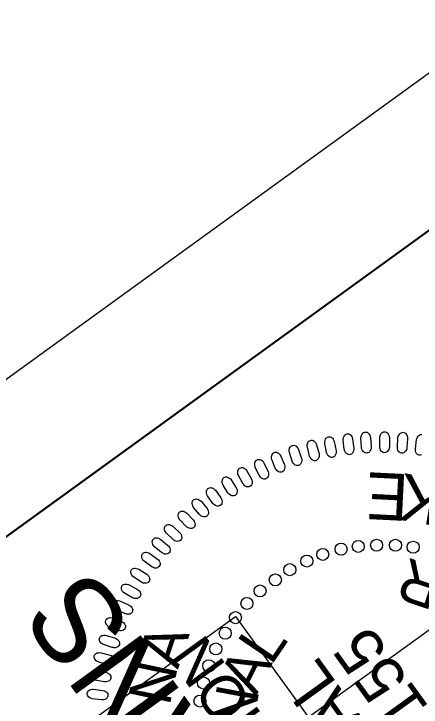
# Model space of a CAD drawing. Extents: x 474925 to 478950, y 494687 to 502905.
# Drawn here: x 475015.1 to 475069.3, y 502284.1 to 502376.4 of the extents above; entities that cross this region are included whole.
import ezdxf

# ---------------------------------------------------------------- set-up
doc = ezdxf.new("R2010")
doc.units = 0
for name, color, linetype in [('Sheet PE Seal Cell', 7, 'Continuous'), ('Sheet Plan CELL', 7, 'Continuous'), ('Sheet Plot Border Inside CELL', 7, 'Continuous'), ('Sheet Plot Border Outside CELL', 7, 'Continuous'), ('Sheet Sticker Incomplete CELL', 7, 'Continuous')]:
    doc.layers.add(name, color=color, linetype=linetype)

msp = doc.modelspace()

# ---------------------------------------------------------------- linework, layer by layer
at = {"layer": 'Sheet PE Seal Cell'}
for points in [[(475061.38, 502318.68), (475061.305, 502319.905), (475061.329, 502320.126), (475061.372, 502320.268), (475061.474, 502320.445), (475061.564, 502320.56), (475061.672, 502320.647), (475061.774, 502320.692), (475061.885, 502320.719), (475061.997, 502320.706), (475062.119, 502320.684), (475062.227, 502320.63), (475062.337, 502320.537), (475062.402, 502320.461), (475062.478, 502320.315), (475062.549, 502320.14), (475062.581, 502319.982), (475062.665, 502318.728), (475062.652, 502318.558), (475062.616, 502318.416), (475062.537, 502318.251), (475062.433, 502318.105), (475062.341, 502318.019), (475062.188, 502317.95), (475062.04, 502317.921), (475061.889, 502317.952), (475061.781, 502317.995), (475061.648, 502318.087), (475061.518, 502318.249), (475061.44, 502318.424), (475061.402, 502318.552)], [(475063.81, 502318.76), (475063.813, 502319.987), (475063.851, 502320.206), (475063.903, 502320.346), (475064.015, 502320.515), (475064.113, 502320.624), (475064.226, 502320.704), (475064.33, 502320.744), (475064.442, 502320.763), (475064.554, 502320.743), (475064.674, 502320.713), (475064.778, 502320.654), (475064.882, 502320.553), (475064.943, 502320.473), (475065.01, 502320.323), (475065.069, 502320.144), (475065.091, 502319.984), (475065.096, 502318.728), (475065.073, 502318.558), (475065.028, 502318.419), (475064.938, 502318.259), (475064.826, 502318.12), (475064.729, 502318.04), (475064.571, 502317.98), (475064.422, 502317.961), (475064.273, 502318.001), (475064.168, 502318.051), (475064.04, 502318.151), (475063.921, 502318.321), (475063.855, 502318.501), (475063.825, 502318.63)], [(475066.158, 502318.725), (475066.237, 502319.949), (475066.288, 502320.165), (475066.349, 502320.302), (475066.472, 502320.464), (475066.576, 502320.567), (475066.694, 502320.639), (475066.8, 502320.672), (475066.914, 502320.684), (475067.024, 502320.657), (475067.142, 502320.62), (475067.242, 502320.554), (475067.34, 502320.447), (475067.395, 502320.363), (475067.452, 502320.21), (475067.5, 502320.027), (475067.512, 502319.866), (475067.439, 502318.612), (475067.405, 502318.444), (475067.351, 502318.308), (475067.252, 502318.155), (475067.131, 502318.022), (475067.028, 502317.949), (475066.868, 502317.899), (475066.717, 502317.89), (475066.571, 502317.939), (475066.47, 502317.995), (475066.349, 502318.103), (475066.241, 502318.28), (475066.185, 502318.463), (475066.164, 502318.595)], [(475056.729, 502318.011), (475056.501, 502319.216), (475056.498, 502319.439), (475056.523, 502319.585), (475056.602, 502319.773), (475056.677, 502319.899), (475056.772, 502319.998), (475056.867, 502320.057), (475056.974, 502320.097), (475057.088, 502320.098), (475057.211, 502320.09), (475057.325, 502320.052), (475057.446, 502319.973), (475057.52, 502319.906), (475057.614, 502319.771), (475057.705, 502319.606), (475057.757, 502319.453), (475057.998, 502318.22), (475058.007, 502318.049), (475057.989, 502317.903), (475057.93, 502317.73), (475057.846, 502317.572), (475057.766, 502317.476), (475057.622, 502317.388), (475057.479, 502317.34), (475057.325, 502317.352), (475057.213, 502317.382), (475057.069, 502317.456), (475056.92, 502317.601), (475056.821, 502317.764), (475056.768, 502317.886)], [(475059.084, 502318.421), (475058.932, 502319.638), (475058.942, 502319.86), (475058.977, 502320.006), (475059.067, 502320.188), (475059.15, 502320.309), (475059.252, 502320.402), (475059.35, 502320.454), (475059.459, 502320.488), (475059.573, 502320.482), (475059.695, 502320.467), (475059.806, 502320.421), (475059.923, 502320.334), (475059.992, 502320.263), (475060.077, 502320.122), (475060.158, 502319.951), (475060.201, 502319.797), (475060.363, 502318.55), (475060.362, 502318.379), (475060.335, 502318.235), (475060.265, 502318.066), (475060.171, 502317.913), (475060.084, 502317.822), (475059.937, 502317.743), (475059.79, 502317.705), (475059.637, 502317.726), (475059.527, 502317.763), (475059.388, 502317.846), (475059.249, 502317.999), (475059.16, 502318.17), (475059.114, 502318.294)], [(475052.158, 502316.828), (475051.781, 502317.996), (475051.749, 502318.217), (475051.756, 502318.366), (475051.811, 502318.561), (475051.869, 502318.695), (475051.952, 502318.806), (475052.039, 502318.876), (475052.139, 502318.929), (475052.252, 502318.945), (475052.376, 502318.953), (475052.493, 502318.929), (475052.624, 502318.865), (475052.705, 502318.808), (475052.815, 502318.686), (475052.927, 502318.534), (475052.998, 502318.389), (475053.39, 502317.195), (475053.421, 502317.027), (475053.421, 502316.88), (475053.385, 502316.701), (475053.321, 502316.534), (475053.254, 502316.428), (475053.122, 502316.323), (475052.985, 502316.258), (475052.832, 502316.25), (475052.717, 502316.265), (475052.565, 502316.321), (475052.399, 502316.446), (475052.28, 502316.596), (475052.212, 502316.71)], [(475054.473, 502317.516), (475054.17, 502318.705), (475054.152, 502318.926), (475054.168, 502319.074), (475054.235, 502319.267), (475054.302, 502319.397), (475054.391, 502319.502), (475054.483, 502319.566), (475054.587, 502319.613), (475054.7, 502319.622), (475054.823, 502319.622), (475054.94, 502319.59), (475055.066, 502319.519), (475055.144, 502319.456), (475055.245, 502319.328), (475055.348, 502319.169), (475055.409, 502319.02), (475055.726, 502317.804), (475055.746, 502317.634), (475055.737, 502317.488), (475055.689, 502317.311), (475055.616, 502317.148), (475055.541, 502317.046), (475055.404, 502316.95), (475055.264, 502316.894), (475055.109, 502316.896), (475054.995, 502316.918), (475054.847, 502316.983), (475054.69, 502317.118), (475054.58, 502317.276), (475054.52, 502317.394)], [(475049.905, 502315.904), (475049.456, 502317.046), (475049.411, 502317.264), (475049.407, 502317.413), (475049.45, 502317.612), (475049.5, 502317.749), (475049.576, 502317.865), (475049.658, 502317.94), (475049.755, 502317.999), (475049.866, 502318.022), (475049.989, 502318.038), (475050.108, 502318.021), (475050.242, 502317.966), (475050.327, 502317.914), (475050.445, 502317.799), (475050.566, 502317.654), (475050.645, 502317.514), (475051.113, 502316.348), (475051.154, 502316.181), (475051.163, 502316.035), (475051.138, 502315.854), (475051.085, 502315.683), (475051.024, 502315.574), (475050.9, 502315.46), (475050.768, 502315.386), (475050.614, 502315.369), (475050.498, 502315.377), (475050.343, 502315.423), (475050.17, 502315.537), (475050.041, 502315.68), (475049.967, 502315.789)], [(475047.761, 502314.946), (475047.241, 502316.057), (475047.182, 502316.271), (475047.169, 502316.419), (475047.199, 502316.621), (475047.241, 502316.762), (475047.308, 502316.881), (475047.386, 502316.962), (475047.48, 502317.028), (475047.589, 502317.057), (475047.71, 502317.08), (475047.831, 502317.071), (475047.968, 502317.024), (475048.056, 502316.978), (475048.18, 502316.871), (475048.31, 502316.734), (475048.398, 502316.599), (475048.938, 502315.464), (475048.989, 502315.301), (475049.008, 502315.155), (475048.994, 502314.973), (475048.952, 502314.799), (475048.898, 502314.685), (475048.781, 502314.565), (475048.654, 502314.483), (475048.502, 502314.456), (475048.386, 502314.457), (475048.229, 502314.493), (475048.049, 502314.596), (475047.911, 502314.73), (475047.83, 502314.835)], [(475045.595, 502313.867), (475045.006, 502314.944), (475044.933, 502315.154), (475044.912, 502315.301), (475044.928, 502315.505), (475044.961, 502315.647), (475045.021, 502315.77), (475045.094, 502315.856), (475045.183, 502315.927), (475045.291, 502315.963), (475045.41, 502315.994), (475045.53, 502315.992), (475045.67, 502315.955), (475045.761, 502315.914), (475045.892, 502315.815), (475046.03, 502315.686), (475046.127, 502315.557), (475046.736, 502314.458), (475046.799, 502314.298), (475046.826, 502314.154), (475046.824, 502313.972), (475046.793, 502313.795), (475046.746, 502313.679), (475046.636, 502313.551), (475046.515, 502313.462), (475046.364, 502313.425), (475046.249, 502313.418), (475046.089, 502313.444), (475045.904, 502313.536), (475045.758, 502313.661), (475045.67, 502313.761)], [(475043.602, 502312.63), (475042.946, 502313.667), (475042.861, 502313.872), (475042.83, 502314.018), (475042.834, 502314.222), (475042.858, 502314.367), (475042.91, 502314.493), (475042.977, 502314.583), (475043.062, 502314.66), (475043.167, 502314.703), (475043.284, 502314.741), (475043.404, 502314.747), (475043.546, 502314.718), (475043.639, 502314.683), (475043.776, 502314.592), (475043.923, 502314.472), (475044.027, 502314.349), (475044.705, 502313.291), (475044.776, 502313.136), (475044.812, 502312.994), (475044.822, 502312.811), (475044.802, 502312.634), (475044.763, 502312.514), (475044.662, 502312.379), (475044.546, 502312.282), (475044.398, 502312.237), (475044.283, 502312.223), (475044.123, 502312.239), (475043.931, 502312.319), (475043.778, 502312.435), (475043.684, 502312.528)], [(475041.605, 502311.225), (475040.886, 502312.219), (475040.788, 502312.419), (475040.748, 502312.563), (475040.74, 502312.766), (475040.754, 502312.912), (475040.799, 502313.042), (475040.86, 502313.135), (475040.939, 502313.217), (475041.042, 502313.267), (475041.156, 502313.313), (475041.276, 502313.326), (475041.419, 502313.306), (475041.514, 502313.277), (475041.657, 502313.195), (475041.81, 502313.085), (475041.922, 502312.969), (475042.665, 502311.955), (475042.746, 502311.805), (475042.791, 502311.664), (475042.812, 502311.483), (475042.803, 502311.304), (475042.771, 502311.182), (475042.679, 502311.042), (475042.57, 502310.938), (475042.425, 502310.883), (475042.311, 502310.862), (475042.15, 502310.868), (475041.954, 502310.936), (475041.794, 502311.042), (475041.693, 502311.129)], [(475039.805, 502309.738), (475039.026, 502310.685), (475038.915, 502310.878), (475038.866, 502311.018), (475038.845, 502311.221), (475038.85, 502311.367), (475038.886, 502311.5), (475038.942, 502311.597), (475039.015, 502311.684), (475039.115, 502311.74), (475039.226, 502311.793), (475039.345, 502311.813), (475039.489, 502311.803), (475039.586, 502311.779), (475039.733, 502311.707), (475039.894, 502311.606), (475040.012, 502311.498), (475040.817, 502310.532), (475040.907, 502310.387), (475040.961, 502310.25), (475040.994, 502310.071), (475040.996, 502309.892), (475040.972, 502309.768), (475040.889, 502309.622), (475040.786, 502309.512), (475040.645, 502309.448), (475040.532, 502309.419), (475040.371, 502309.416), (475040.171, 502309.47), (475040.005, 502309.566), (475039.9, 502309.647)], [(475038.033, 502308.154), (475037.195, 502309.05), (475037.073, 502309.235), (475037.015, 502309.373), (475036.981, 502309.573), (475036.977, 502309.72), (475037.004, 502309.855), (475037.053, 502309.955), (475037.122, 502310.046), (475037.217, 502310.108), (475037.325, 502310.168), (475037.443, 502310.197), (475037.587, 502310.195), (475037.685, 502310.177), (475037.837, 502310.114), (475038.003, 502310.024), (475038.129, 502309.923), (475038.993, 502309.01), (475039.091, 502308.871), (475039.154, 502308.738), (475039.198, 502308.561), (475039.211, 502308.382), (475039.195, 502308.257), (475039.121, 502308.106), (475039.025, 502307.989), (475038.889, 502307.917), (475038.779, 502307.882), (475038.618, 502307.868), (475038.414, 502307.91), (475038.243, 502307.995), (475038.132, 502308.07)], [(475036.291, 502306.401), (475035.398, 502307.242), (475035.264, 502307.42), (475035.198, 502307.553), (475035.152, 502307.752), (475035.139, 502307.897), (475035.157, 502308.034), (475035.2, 502308.137), (475035.263, 502308.233), (475035.354, 502308.3), (475035.459, 502308.367), (475035.573, 502308.402), (475035.717, 502308.41), (475035.817, 502308.399), (475035.972, 502308.345), (475036.144, 502308.265), (475036.275, 502308.172), (475037.195, 502307.315), (475037.302, 502307.183), (475037.373, 502307.055), (475037.427, 502306.88), (475037.452, 502306.703), (475037.444, 502306.577), (475037.38, 502306.421), (475037.291, 502306.299), (475037.16, 502306.218), (475037.052, 502306.176), (475036.892, 502306.152), (475036.687, 502306.181), (475036.509, 502306.255), (475036.395, 502306.323)], [(475034.764, 502304.666), (475033.82, 502305.45), (475033.676, 502305.618), (475033.601, 502305.748), (475033.542, 502305.943), (475033.52, 502306.087), (475033.53, 502306.224), (475033.567, 502306.33), (475033.623, 502306.429), (475033.71, 502306.503), (475033.81, 502306.576), (475033.921, 502306.618), (475034.066, 502306.635), (475034.165, 502306.63), (475034.323, 502306.586), (475034.5, 502306.517), (475034.637, 502306.433), (475035.608, 502305.636), (475035.724, 502305.51), (475035.803, 502305.386), (475035.868, 502305.215), (475035.904, 502305.04), (475035.904, 502304.914), (475035.849, 502304.755), (475035.769, 502304.628), (475035.643, 502304.538), (475035.538, 502304.49), (475035.38, 502304.455), (475035.173, 502304.472), (475034.992, 502304.535), (475034.873, 502304.595)], [(475033.441, 502302.788), (475032.449, 502303.511), (475032.294, 502303.671), (475032.212, 502303.795), (475032.141, 502303.986), (475032.109, 502304.129), (475032.111, 502304.267), (475032.141, 502304.374), (475032.191, 502304.477), (475032.273, 502304.556), (475032.368, 502304.635), (475032.477, 502304.684), (475032.62, 502304.709), (475032.72, 502304.711), (475032.881, 502304.677), (475033.06, 502304.62), (475033.203, 502304.544), (475034.223, 502303.809), (475034.346, 502303.691), (475034.432, 502303.572), (475034.508, 502303.406), (475034.555, 502303.234), (475034.562, 502303.108), (475034.518, 502302.945), (475034.446, 502302.813), (475034.325, 502302.716), (475034.224, 502302.661), (475034.068, 502302.617), (475033.861, 502302.62), (475033.676, 502302.671), (475033.554, 502302.724)], [(475032.079, 502300.723), (475031.044, 502301.382), (475030.88, 502301.532), (475030.789, 502301.65), (475030.707, 502301.836), (475030.667, 502301.977), (475030.66, 502302.115), (475030.682, 502302.224), (475030.726, 502302.33), (475030.803, 502302.413), (475030.893, 502302.498), (475030.999, 502302.554), (475031.14, 502302.589), (475031.239, 502302.597), (475031.401, 502302.573), (475031.585, 502302.527), (475031.731, 502302.46), (475032.795, 502301.791), (475032.926, 502301.681), (475033.02, 502301.568), (475033.106, 502301.407), (475033.163, 502301.237), (475033.179, 502301.112), (475033.144, 502300.947), (475033.081, 502300.811), (475032.967, 502300.706), (475032.868, 502300.645), (475032.716, 502300.591), (475032.509, 502300.582), (475032.321, 502300.621), (475032.196, 502300.666)], [(475030.903, 502298.662), (475029.829, 502299.255), (475029.655, 502299.394), (475029.558, 502299.507), (475029.464, 502299.687), (475029.415, 502299.825), (475029.399, 502299.962), (475029.415, 502300.073), (475029.452, 502300.181), (475029.523, 502300.269), (475029.607, 502300.359), (475029.71, 502300.422), (475029.848, 502300.465), (475029.947, 502300.479), (475030.111, 502300.466), (475030.296, 502300.431), (475030.447, 502300.374), (475031.551, 502299.773), (475031.688, 502299.671), (475031.789, 502299.564), (475031.884, 502299.409), (475031.953, 502299.243), (475031.976, 502299.12), (475031.952, 502298.953), (475031.897, 502298.812), (475031.79, 502298.701), (475031.696, 502298.634), (475031.547, 502298.57), (475031.341, 502298.548), (475031.151, 502298.576), (475031.023, 502298.613)], [(475029.865, 502296.543), (475028.756, 502297.068), (475028.574, 502297.196), (475028.47, 502297.302), (475028.364, 502297.476), (475028.307, 502297.611), (475028.283, 502297.747), (475028.292, 502297.858), (475028.321, 502297.968), (475028.387, 502298.061), (475028.465, 502298.156), (475028.564, 502298.225), (475028.699, 502298.277), (475028.796, 502298.297), (475028.961, 502298.294), (475029.148, 502298.271), (475029.302, 502298.223), (475030.441, 502297.693), (475030.585, 502297.6), (475030.693, 502297.499), (475030.798, 502297.35), (475030.876, 502297.19), (475030.907, 502297.067), (475030.894, 502296.9), (475030.848, 502296.756), (475030.748, 502296.638), (475030.659, 502296.565), (475030.514, 502296.492), (475030.309, 502296.457), (475030.118, 502296.473), (475029.988, 502296.502)], [(475028.944, 502294.32), (475027.805, 502294.773), (475027.614, 502294.89), (475027.504, 502294.99), (475027.388, 502295.156), (475027.322, 502295.288), (475027.289, 502295.421), (475027.291, 502295.533), (475027.314, 502295.645), (475027.374, 502295.741), (475027.446, 502295.842), (475027.54, 502295.916), (475027.672, 502295.977), (475027.768, 502296.003), (475027.932, 502296.01), (475028.121, 502295.999), (475028.277, 502295.961), (475029.447, 502295.504), (475029.596, 502295.42), (475029.709, 502295.326), (475029.825, 502295.184), (475029.913, 502295.028), (475029.951, 502294.908), (475029.949, 502294.74), (475029.912, 502294.594), (475029.82, 502294.47), (475029.735, 502294.391), (475029.595, 502294.31), (475029.393, 502294.261), (475029.201, 502294.266), (475029.07, 502294.286)], [(475028.189, 502292.044), (475027.024, 502292.426), (475026.827, 502292.529), (475026.71, 502292.622), (475026.583, 502292.782), (475026.51, 502292.908), (475026.469, 502293.039), (475026.463, 502293.151), (475026.479, 502293.264), (475026.533, 502293.365), (475026.599, 502293.469), (475026.688, 502293.55), (475026.815, 502293.618), (475026.91, 502293.65), (475027.073, 502293.668), (475027.262, 502293.669), (475027.421, 502293.641), (475028.617, 502293.257), (475028.771, 502293.183), (475028.891, 502293.097), (475029.014, 502292.962), (475029.112, 502292.812), (475029.158, 502292.695), (475029.166, 502292.527), (475029.138, 502292.378), (475029.054, 502292.249), (475028.974, 502292.165), (475028.84, 502292.075), (475028.641, 502292.014), (475028.45, 502292.006), (475028.317, 502292.018)], [(475027.57, 502289.792), (475026.382, 502290.1), (475026.179, 502290.191), (475026.057, 502290.277), (475025.921, 502290.428), (475025.839, 502290.55), (475025.79, 502290.678), (475025.777, 502290.789), (475025.786, 502290.903), (475025.834, 502291.006), (475025.893, 502291.115), (475025.977, 502291.201), (475026.1, 502291.277), (475026.192, 502291.315), (475026.354, 502291.343), (475026.542, 502291.355), (475026.702, 502291.338), (475027.921, 502291.03), (475028.079, 502290.966), (475028.203, 502290.887), (475028.335, 502290.76), (475028.442, 502290.617), (475028.495, 502290.503), (475028.514, 502290.336), (475028.495, 502290.186), (475028.419, 502290.052), (475028.345, 502289.963), (475028.217, 502289.864), (475028.023, 502289.791), (475027.832, 502289.771), (475027.699, 502289.775)], [(475027.1, 502287.463), (475025.896, 502287.695), (475025.688, 502287.773), (475025.56, 502287.851), (475025.415, 502287.993), (475025.326, 502288.109), (475025.269, 502288.234), (475025.249, 502288.345), (475025.251, 502288.459), (475025.292, 502288.565), (475025.344, 502288.677), (475025.422, 502288.768), (475025.54, 502288.852), (475025.63, 502288.895), (475025.789, 502288.933), (475025.977, 502288.958), (475026.138, 502288.95), (475027.373, 502288.719), (475027.535, 502288.665), (475027.664, 502288.595), (475027.803, 502288.477), (475027.92, 502288.34), (475027.98, 502288.229), (475028.009, 502288.064), (475028, 502287.913), (475027.933, 502287.774), (475027.864, 502287.681), (475027.742, 502287.575), (475027.553, 502287.49), (475027.363, 502287.458), (475027.23, 502287.453)], [(475026.752, 502285.057), (475025.535, 502285.213), (475025.322, 502285.278), (475025.19, 502285.347), (475025.036, 502285.48), (475024.94, 502285.591), (475024.875, 502285.712), (475024.849, 502285.821), (475024.843, 502285.935), (475024.877, 502286.043), (475024.922, 502286.158), (475024.995, 502286.254), (475025.107, 502286.345), (475025.194, 502286.395), (475025.351, 502286.442), (475025.537, 502286.479), (475025.697, 502286.481), (475026.945, 502286.328), (475027.11, 502286.284), (475027.243, 502286.222), (475027.39, 502286.112), (475027.514, 502285.984), (475027.581, 502285.877), (475027.621, 502285.714), (475027.621, 502285.563), (475027.562, 502285.42), (475027.5, 502285.323), (475027.385, 502285.209), (475027.201, 502285.112), (475027.015, 502285.068), (475026.882, 502285.055)]]:
    msp.add_lwpolyline(points, close=True, dxfattribs=at)
msp.add_lwpolyline([(475069.38, 502317.667), (475069.217, 502317.627), (475069.066, 502317.627), (475068.923, 502317.686), (475068.825, 502317.749), (475068.712, 502317.863), (475068.615, 502318.046), (475068.571, 502318.234), (475068.558, 502318.365), (475068.559, 502318.496), (475068.716, 502319.713), (475068.78, 502319.926), (475068.85, 502320.058), (475068.983, 502320.212), (475069.093, 502320.308), (475069.215, 502320.373), (475069.323, 502320.399), (475069.437, 502320.404)], dxfattribs=at)
for centre in [(475058.666, 502305.125), (475060.951, 502305.501), (475063.4, 502305.651), (475065.909, 502305.649), (475068.263, 502305.386), (475056.216, 502304.434), (475054.106, 502303.545), (475051.839, 502302.397), (475049.907, 502301.034), (475047.873, 502299.563), (475046.124, 502297.904), (475044.593, 502296.01), (475043.234, 502293.946), (475041.983, 502291.839), (475041.051, 502289.593), (475040.342, 502287.311), (475039.87, 502284.905)]:
    msp.add_circle(centre, 0.801, dxfattribs=at)
at = {"layer": 'Sheet Plan CELL'}
for points in [[(474953.05, 502262.647), (475832.788, 501047.669), (476683.252, 501663.47), (475803.528, 502878.428)], [(475042.137, 502203.66), (474983.486, 502284.639), (475074.61, 502350.635), (475133.268, 502269.646)]]:
    msp.add_lwpolyline(points, close=True, dxfattribs=at)
at = {"layer": 'Sheet Plot Border Inside CELL'}
msp.add_lwpolyline([(476807.904, 501495.6), (475830.83, 502844.985), (474976.319, 502226.269), (475953.391, 500876.866)], close=True, dxfattribs=at)
at = {"layer": 'Sheet Plot Border Outside CELL'}
msp.add_lwpolyline([(475811.793, 502905.401), (476799.127, 501541.824), (475912.215, 500899.631), (474924.88, 502263.208)], close=True, dxfattribs=at)
at = {"layer": 'Sheet Sticker Incomplete CELL'}
msp.add_lwpolyline([(475130.803, 502177.117), (475111.769, 502163.335), (475025.557, 502282.4), (475044.591, 502296.182)], close=True, dxfattribs=at)

# ---------------------------------------------------------------- texts
at = {"layer": 'Sheet PE Seal Cell'}
for s, height, rotation, p in [('E', 6.236, 177.17568, (475067.742, 502315.106)), ('K', 6.236, 170.33002, (475072.472, 502314.327)), ('R', 5.669, 161.57098, (475072.645, 502302.323)), ('A', 5.669, 71.58024, (475036.928, 502289.059)), ('L', 5.669, 55.73828, (475049.34, 502289.537)), ('46155', 6.2363, 125.88878, (475075.939, 502276.488)), ('A', 5.669, 63.67807, (475047.35, 502285.475)), ('SEAL', 6.2363, 125.88878, (475068.018, 502273.652)), ('N', 5.669, 78.0696, (475035.814, 502284.153)), ('N', 5.669, 79.55767, (475046.812, 502280.965))]:
    msp.add_text(s, height=height, rotation=rotation, dxfattribs=at).set_placement(p)
at = {"layer": 'Sheet Sticker Incomplete CELL'}
for s, height, p in [('INCOMPLETE PLANS', 11.52, (475116.078, 502177.504)), ('DO NOT USE FOR R/W ACQUISITION', 5.76, (475119.801, 502184.213))]:
    msp.add_text(s, height=height, rotation=125.90742, dxfattribs=at).set_placement(p)

doc.saveas('drawing.dxf')
